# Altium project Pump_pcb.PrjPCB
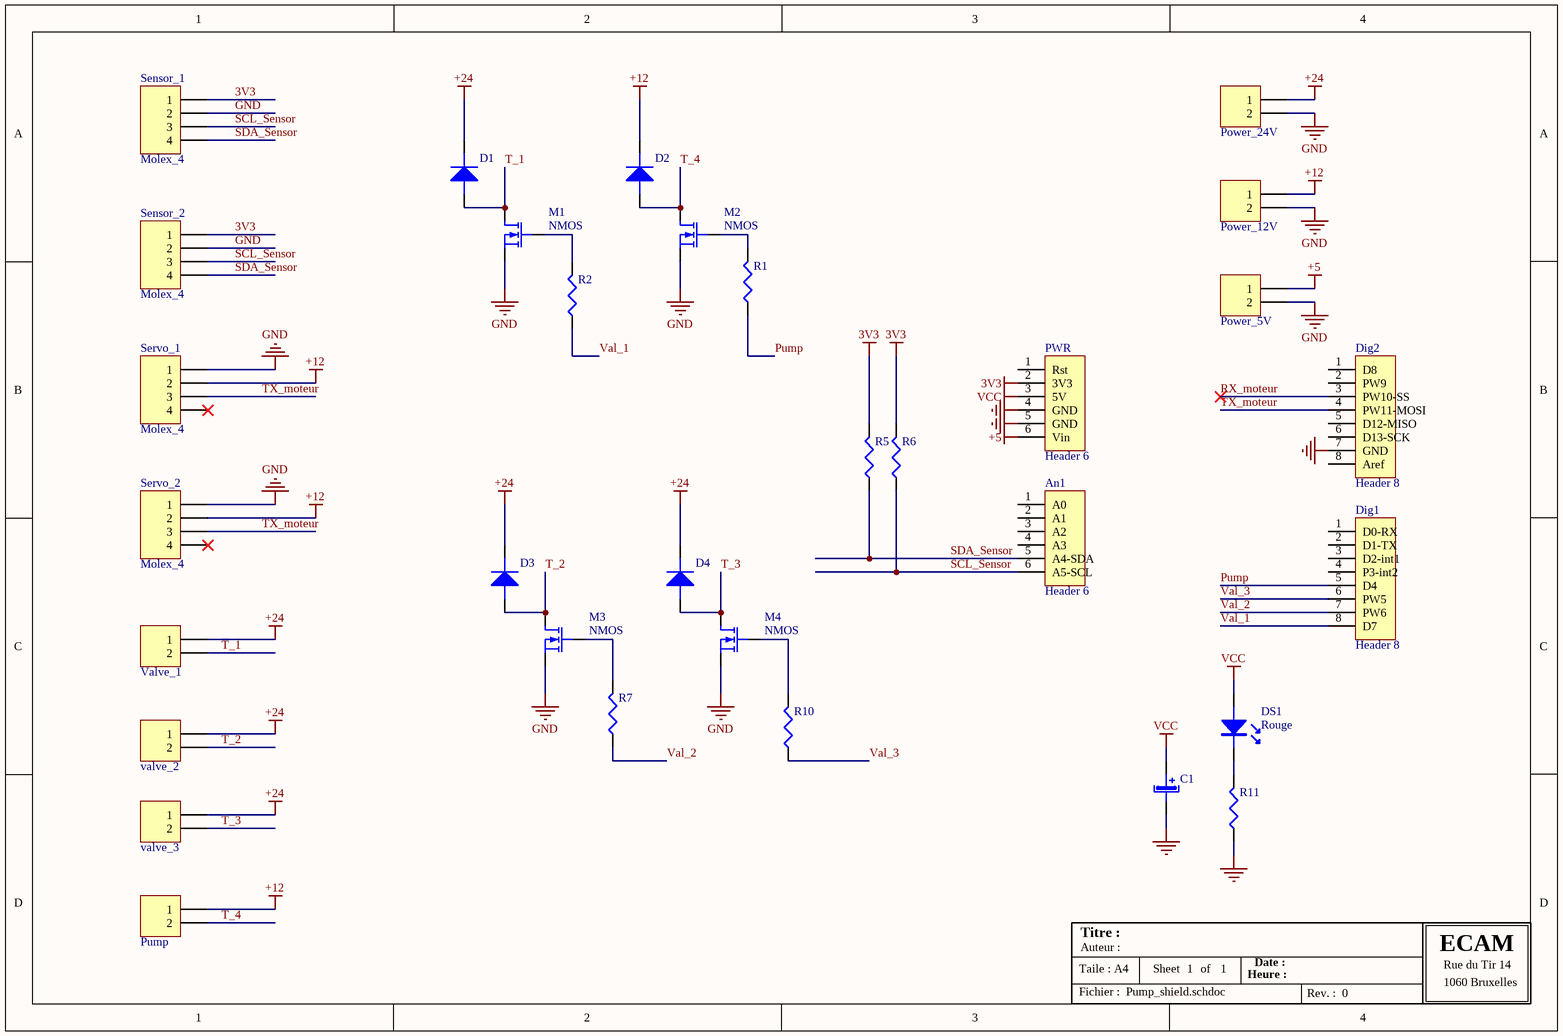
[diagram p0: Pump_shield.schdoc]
1 sheet, 32 parts. Net scope: global (net labels, ports and power ports of the same name join across sheets).
Board file: Pump_shield.pcbdoc

## Sheet Pump_shield.schdoc
size A4; Organization: ECAM; Revision: 0; SheetNumber: 1; SheetTotal: 1

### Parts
An1  Header 6  [HDR1X6]
C1  Cond pol radial  [CAPPR1.5-4x5]  (value not drawn)
D1  Diode  [DIO10.46-5.3x2.8]  (value not drawn)
D2  Diode  [DIO10.46-5.3x2.8]  (value not drawn)
D3  Diode  [DIO10.46-5.3x2.8]  (value not drawn)
D4  Diode  [DIO10.46-5.3x2.8]  (value not drawn)
Dig1  Header 8  [HDR1X8]
Dig2  Header 8  [HDR1X8]
DS1  Color: Rouge  [LED 0.1]  (hidden comment: LED)
M1  value NMOS  [TO-92]  (hidden comment: MOSFET-N)
M2  value NMOS  [TO-220 V]  (hidden comment: MOSFET-N)
M3  value NMOS  [TO-92]  (hidden comment: MOSFET-N)
M4  value NMOS  [TO-92]  (hidden comment: MOSFET-N)
Power_5V  Molex_2  [Header_2Ecam]  (value not drawn)
Power_12V  Molex_2  [Header_2Ecam]  (value not drawn)
Power_24V  Molex_2  [Header_2Ecam]  (value not drawn)
Pump  Molex_2  [Header_2Ecam]  (value not drawn)
PWR  Header 6  [HDR1X6]
R1  Résistance  [AXIAL-0.4]  (value not drawn)
R2  Résistance  [AXIAL-0.4]  (value not drawn)
R5  Résistance  [AXIAL-0.4]  (value not drawn)
R6  Résistance  [AXIAL-0.4]  (value not drawn)
R7  Résistance  [AXIAL-0.4]  (value not drawn)
R10  Résistance  [AXIAL-0.4]  (value not drawn)
R11  Résistance  [AXIAL-0.4]  (value not drawn)
Sensor_1  Molex_4  [Header4_ecam]
Sensor_2  Molex_4  [Header4_ecam]
Servo_1  Molex_4  [Header4_ecam]
Servo_2  Molex_4  [Header4_ecam]
Valve_1  Molex_2  [Header_2Ecam]  (value not drawn)
valve_2  Molex_2  [Header_2Ecam]  (value not drawn)
valve_3  Molex_2  [Header_2Ecam]  (value not drawn)

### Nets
3V3: PWR.2(3V3) R5.2 R6.2 Sensor_1.1 Sensor_2.1
+5: Power_5V.1 PWR.6(Vin)
+12: D2.2(K) Power_12V.1 Pump.1 Servo_1.2 Servo_2.2
+24: D1.2(K) D3.2(K) D4.2(K) Power_24V.1 Valve_1.1 valve_2.1 valve_3.1
GND: C1.2(-) Dig2.7(GND) M1.S M2.S M3.S M4.S Power_5V.2 Power_12V.2 Power_24V.2 PWR.4(GND) PWR.5(GND) R11.1 Sensor_1.2 Sensor_2.2 Servo_1.1 Servo_2.1
VCC: C1.1(+) DS1.1(A) PWR.3(5V)
Pump: Dig1.5(D4) R1.1
RX_moteur: Dig2.3(PW10-SS)
SCL_Sensor: An1.6(A5-SCL) R6.1 Sensor_1.3 Sensor_2.3
SDA_Sensor: An1.5(A4-SDA) R5.1 Sensor_1.4 Sensor_2.4
T_1: D1.1(A) M1.D Valve_1.2
T_2: D3.1(A) M3.D valve_2.2
T_3: D4.1(A) M4.D valve_3.2
T_4: D2.1(A) M2.D Pump.2
TX_moteur: Dig2.4(PW11-MOSI) Servo_1.3 Servo_2.3
Val_1: Dig1.8(D7) R2.1
Val_2: Dig1.7(PW6) R7.1
Val_3: Dig1.6(PW5) R10.1
NetDS1_2: DS1.2(K) R11.2
NetM1_G: M1.G R2.2
NetM2_G: M2.G R1.2
NetM3_G: M3.G R7.2
NetM4_G: M4.G R10.2

Not connected (* = marked no-connect by the designer): An1 1(A0) 2(A1) 3(A2) 4(A3); Dig1 1(D0-RX) 2(D1-TX) 3(D2-int1) 4(P3-int2); Dig2 1(D8) 2(PW9) 5(D12-MISO) 6(D13-SCK) 8(Aref); PWR 1(Rst); Servo_1 4*; Servo_2 4*

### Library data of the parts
An1 PWR = Header 6: Header, 6-Pin
C1 = Cond pol radial: Condensateur polatisé; Type: Condensateur polarisé debout
D1-D4 = Diode: Type: Diode standard
Dig1 Dig2 = Header 8: Header, 8-Pin
M1-M4 = MOSFET-N: MOSFET
Power_5V Power_12V Power_24V Pump Valve_1 valve_2 valve_3 = Molex_2: Header, 2-pin
R1 R2 R5-R7 R10 R11 = Résistance: Résistance standard
Sensor_1 Sensor_2 Servo_1 Servo_2 = Molex_4: Header, 4-Pin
